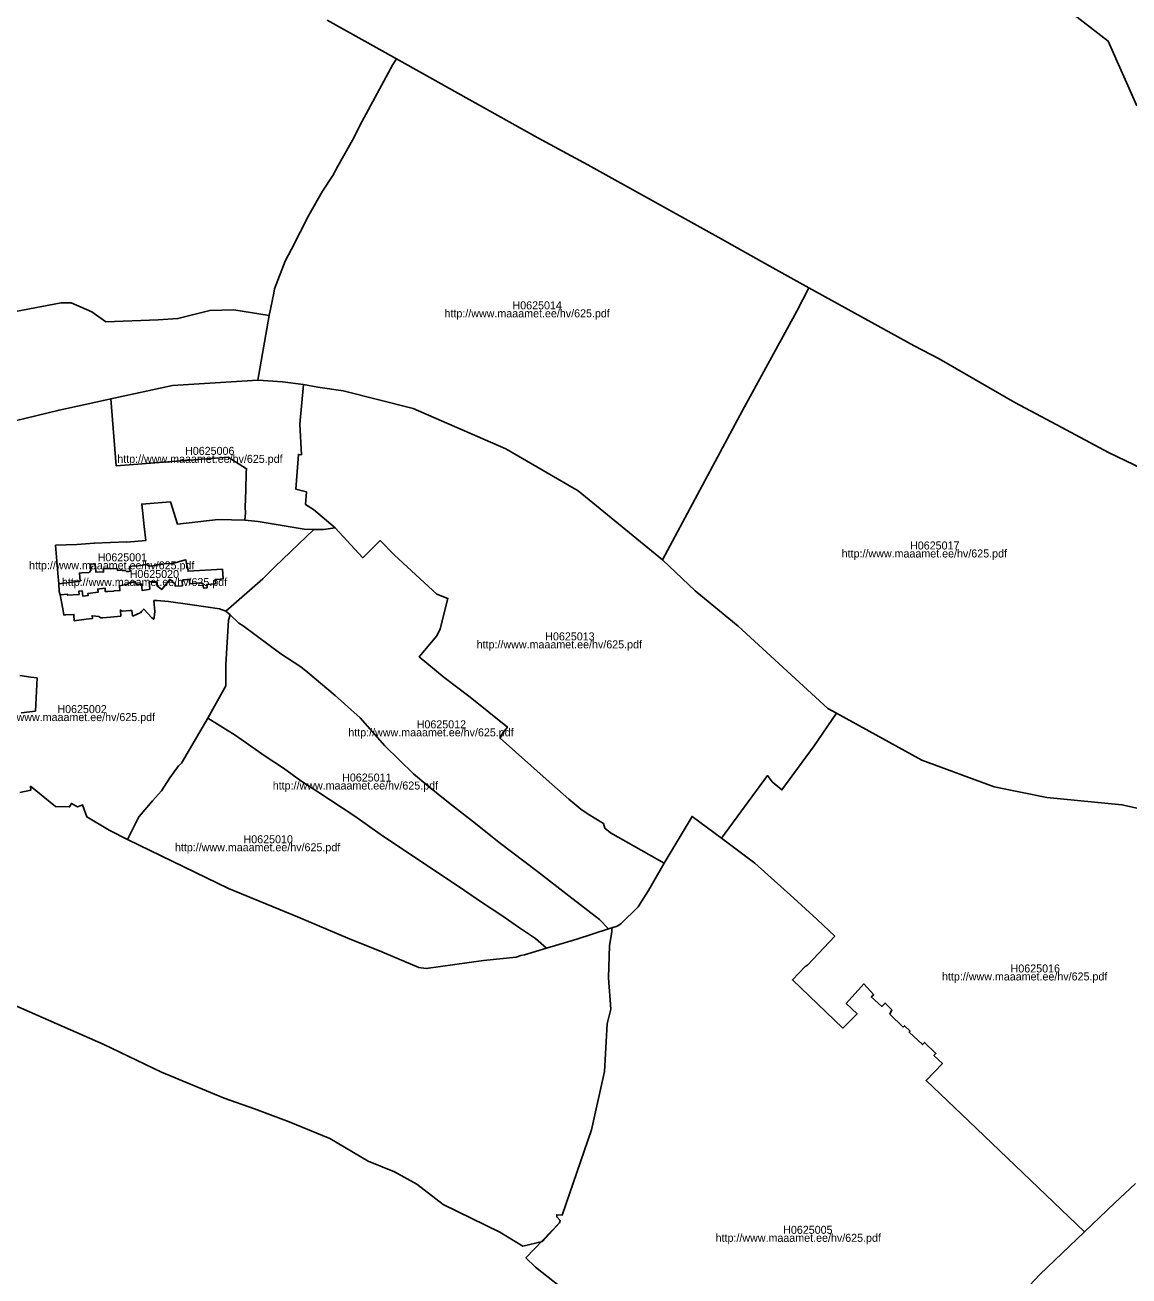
# Model space of a CAD drawing. Extents: x 369010 to 739155, y 6377141 to 6634081.
# Drawn here: x 528995 to 532445, y 6469504 to 6473413 of the extents above; entities that cross this region are included whole.
import ezdxf

# ---------------------------------------------------------------- set-up
doc = ezdxf.new("R2010")
doc.units = 0
for name, color, linetype in [('H_LINK', 7, 'Continuous'), ('H_PIIR', 7, 'Continuous'), ('H_TUNNUS', 7, 'Continuous')]:
    doc.layers.add(name, color=color, linetype=linetype)

msp = doc.modelspace()

# ---------------------------------------------------------------- linework, layer by layer
at = {"layer": 'H_PIIR'}
for points in [[(532469.6799, 6473160.7601), (532380.8399, 6473363), (532136.3301, 6473552.5401)], [(532136.3301, 6473552.5401), (532380.8399, 6473363), (532469.6799, 6473160.7601)], [(529939.2001, 6473428.33), (530156.6701, 6473307.9101), (530144.9, 6473289.3799), (530047.4799, 6473110.31), (530019.01, 6473053.3499), (529972.43, 6472971.79), (529956.8999, 6472943.3101), (529924.5499, 6472894.1199), (529881.85, 6472819.04), (529827.5, 6472712.8899), (529808.0899, 6472675.35), (529774.44, 6472588.62), (529773.15, 6472575.6699), (529758.4499, 6472505.71), (529758.33, 6472505.15), (529648.1, 6472522.84), (529572.37, 6472521.4499), (529472.8699, 6472495.68), (529411.2401, 6472492.2), (529247.44, 6472485.95), (529203.63, 6472516.58), (529139.78, 6472545.1301), (529107.85, 6472545.1301), (528965.28, 6472517.9799)], [(532461.29, 6472038.9899), (532381.79, 6472077.7801), (532219.7999, 6472163.57), (532089.11, 6472233.85), (531852.23, 6472370.04), (531774.5101, 6472410.35), (531444.78, 6472592.07), (531323.01, 6472659.61), (531161.88, 6472750.13), (530754.18, 6472976.5899), (530597.5001, 6473060.8499), (530347.4999, 6473199.9901), (530156.6701, 6473307.9101), (529939.2001, 6473428.33)], [(528965.28, 6472517.9799), (529107.85, 6472545.1301), (529139.78, 6472545.1301), (529203.63, 6472516.58), (529247.44, 6472485.95), (529411.2401, 6472492.2), (529472.8699, 6472495.68), (529572.37, 6472521.4499), (529648.1, 6472522.84), (529758.33, 6472505.15), (529722.2601, 6472303.61), (529456.39, 6472287.1099), (529263, 6472245.1501), (529240.04, 6472240.17), (529101.44, 6472210.1), (528718.62, 6472116.9799)], [(528718.62, 6472116.9799), (529101.44, 6472210.1), (529240.04, 6472240.17), (529263, 6472245.1501), (529280.03, 6472036.1199), (529629.7599, 6472062.6499), (529687.39, 6472026.8899), (529686.68, 6472014.8901), (529684.97, 6471959.33), (529682.9901, 6471906.9199), (529683.76, 6471888.69), (529682.2899, 6471866.42), (529598.33, 6471868.2599), (529472.15, 6471853.4001), (529449.47, 6471923.2401), (529360.08, 6471916.2001), (529367.01, 6471846.09), (529372.6001, 6471802.5199), (529313.1301, 6471797.3199), (529313.77, 6471798.07), (529211.7, 6471794.12), (529211.4599, 6471794.04), (529156.6699, 6471789.53), (529090.9299, 6471787.66), (529097.57, 6471700.68), (529100.4, 6471666.9399), (529102.3599, 6471643.64), (529104.54, 6471632.4001), (529112.9201, 6471589.25), (529116.2799, 6471569.79), (529123.01, 6471569.9199), (529148.1401, 6471571.6399), (529148.88, 6471551.76), (529186.1401, 6471556.6999), (529205.7601, 6471558.61), (529204.81, 6471567.2001), (529216.1401, 6471565.69), (529225.71, 6471565.4001), (529231.7401, 6471560.39), (529237.25, 6471561.3199), (529261.99, 6471563.0099), (529294.1401, 6471566.42), (529293.25, 6471585.0401), (529299.06, 6471581.34), (529323.5001, 6471583.66), (529328.9, 6471584.09), (529331.33, 6471566.74), (529333.99, 6471567.45), (529355.2501, 6471576.8), (529356.05, 6471576.4701), (529360.53, 6471582.1401), (529366.4, 6471588.31), (529391.4799, 6471561.21), (529396.93, 6471556.6), (529398.4701, 6471562.0101), (529400.46, 6471580.8799), (529397.9801, 6471614.64), (529407.97, 6471615.34), (529443.33, 6471612.32), (529517.77, 6471601.6699), (529602.7401, 6471589.1001), (529623.08, 6471582), (529635.92, 6471569.78), (529631.39, 6471554.03), (529622.67, 6471415.25), (529623.0001, 6471347.9501), (529566.69, 6471247.5701), (529484.17, 6471107.2499), (529474.47, 6471098.1601), (529448.0499, 6471060.41), (529421.86, 6471019.81), (529393.7499, 6470988.6), (529352.3901, 6470940.12), (529346.5701, 6470930.7301), (529315.23, 6470868.71), (529257.7601, 6470897.1499), (529187.9301, 6470938.7699), (529175.0699, 6470976.4001), (529171.0999, 6470974.4599), (529159.37, 6470970.65), (529140.0301, 6470981.08), (529134.53, 6470970.2), (529090.69, 6470970.82), (529012.3, 6471034.85), (529013.1301, 6471021.9901), (528979.13, 6471015.5401)], [(528979.0901, 6471380.45), (529013.18, 6471374.9899), (529032.99, 6471373.2499), (529027.5701, 6471269.4401), (528983.26, 6471264.5)], [(528983.26, 6471264.5), (529027.5701, 6471269.4401), (529032.99, 6471373.2499), (529013.18, 6471374.9899), (528979.0901, 6471380.45)], [(532466, 6469793.78), (532399.72, 6469732.2), (532306.28, 6469642.7799), (531944.6599, 6469988.4799), (531811.2899, 6470114.68), (531862.36, 6470168.12), (531835.94, 6470193.2499), (531841.9399, 6470199.96), (531806.1299, 6470234.16), (531799.71, 6470227.4401), (531758.3099, 6470266.6301), (531761.3101, 6470269.76), (531743.8799, 6470286.39), (531739.9501, 6470282.2601), (531698.3201, 6470322.39), (531704.1801, 6470335.52), (531683.14, 6470356.8), (531672.77, 6470346.7199), (531640.0801, 6470376.1899), (531647.73, 6470383.34), (531616.9701, 6470416.98), (531561.71, 6470356.26), (531595.86, 6470323.57), (531551.1499, 6470279.17), (531393.54, 6470429.2799), (531433.24, 6470470.9001), (531441.13, 6470475.9699), (531525.8201, 6470566.48), (531470.4501, 6470618.4), (531398.1, 6470685.26), (531276.5601, 6470793.8999), (531172.24, 6470872.4601), (531316.15, 6471067.69), (531330.6599, 6471048.21), (531360.46, 6471022.91), (531461.1701, 6471160.73), (531531.5199, 6471262.76), (531798.1099, 6471116.05), (532024.04, 6471032.9601), (532189.06, 6470999.72), (532423.29, 6470976.67), (532513.1101, 6470956.7901)], [(528979.13, 6471015.5401), (529013.1301, 6471021.9901), (529012.3, 6471034.85), (529090.69, 6470970.82), (529134.53, 6470970.2), (529140.0301, 6470981.08), (529159.37, 6470970.65), (529171.0999, 6470974.4599), (529175.0699, 6470976.4001), (529187.9301, 6470938.7699), (529257.7601, 6470897.1499), (529315.23, 6470868.71), (529631.5801, 6470714.75), (529846.2601, 6470626.6299), (530003.6299, 6470560.1), (530110.7, 6470517.38), (530178.78, 6470487.6601), (530226.4301, 6470467.84), (530249.33, 6470465.37), (530428.24, 6470490.21), (530530.36, 6470500.47), (530544.8599, 6470505.61), (530556.62, 6470507.47), (530625.46, 6470529), (530719.6299, 6470556.8099), (530818.81, 6470588.93), (530829.07, 6470592.42), (530828.7099, 6470579.61), (530821.8399, 6470537.47), (530818.65, 6470435.82), (530826.4299, 6470338.0399), (530814.55, 6470291.9399), (530805.8301, 6470143.2401), (530765.4101, 6469961.22), (530673.6075, 6469693.9927), (530656.9601, 6469695.62), (530656.9601, 6469688.85), (530668.03, 6469677.77), (530665.341, 6469669.9427), (530612.5151, 6469612.1542), (530551.0472, 6469597.9678), (530479.5301, 6469640.8568), (530301.7298, 6469727.6403), (530219.1796, 6469791.1405), (530150.3878, 6469829.2405), (530067.8377, 6469863.1073), (529948.2457, 6469934.0157), (529820.1872, 6469985.8742), (529712.2369, 6470026.0909), (529618.0451, 6470059.9577), (529421.1947, 6470141.4495), (529239.161, 6470228.233), (528923.777, 6470366.8749)], [(531019.652, 6469193.3816), (530591.0262, 6469532.049), (530560.599, 6469561.1532), (530665.341, 6469669.9427), (530668.03, 6469677.77), (530656.9601, 6469688.85), (530656.9601, 6469695.62), (530673.6101, 6469694), (530765.4101, 6469961.22), (530805.8301, 6470143.2401), (530814.55, 6470291.9399), (530826.4299, 6470338.0399), (530818.65, 6470435.82), (530821.8399, 6470537.47), (530828.7099, 6470579.61), (530829.07, 6470592.42), (530845.38, 6470597.8301), (530856.79, 6470604.96), (530911.66, 6470657.94), (530921.98, 6470674.24), (530944.2501, 6470708.36), (530992.5399, 6470794.76), (531079.7599, 6470940.17), (531172.24, 6470872.4601), (531276.5601, 6470793.8999), (531398.1, 6470685.26), (531470.4501, 6470618.4), (531525.8201, 6470566.48), (531441.13, 6470475.9699), (531433.24, 6470470.9001), (531393.54, 6470429.2799), (531551.1499, 6470279.17), (531595.86, 6470323.57), (531561.71, 6470356.26), (531616.9701, 6470416.98), (531647.73, 6470383.34), (531640.0801, 6470376.1899), (531672.77, 6470346.7199), (531683.14, 6470356.8), (531704.1801, 6470335.52), (531698.3201, 6470322.39), (531739.9501, 6470282.2601), (531743.8799, 6470286.39), (531761.3101, 6470269.76), (531758.3099, 6470266.6301), (531799.71, 6470227.4401), (531806.1299, 6470234.16), (531841.9399, 6470199.96), (531835.94, 6470193.2499), (531862.36, 6470168.12), (531811.2899, 6470114.68), (531944.6599, 6469988.4799), (532306.28, 6469642.7799), (532166.63, 6469509.1201), (532021.8799, 6469354.4401)], [(532643.2723, 6467471.2918), (532234.0919, 6467984.2334), (531906.0079, 6468383.755), (531469.4446, 6468849.4226), (531441.6633, 6468874.5581), (531469.4446, 6468895.7248), (531684.5701, 6469055.26), (531684.69, 6469055.8), (531734.52, 6469100.32), (531737.9, 6469098.8701), (531743.1, 6469107.9799), (531891.93, 6469240.91), (532021.8799, 6469354.4401), (532166.63, 6469509.1201), (532306.28, 6469642.7799), (532399.72, 6469732.2), (532466, 6469793.78)]]:
    msp.add_lwpolyline(points, dxfattribs=at)
for points in [[(530156.6701, 6473307.9101), (530347.4999, 6473199.9901), (530597.5001, 6473060.8499), (530754.18, 6472976.5899), (531161.88, 6472750.13), (531323.01, 6472659.61), (531444.78, 6472592.07), (531407.06, 6472519.33), (531237.02, 6472208.7801), (530987.74, 6471741.71), (530723.7199, 6471958.07), (530497.78, 6472088.8001), (530208.72, 6472215.1001), (529989.11, 6472270.4901), (529910.49, 6472282.15), (529865.57, 6472289.77), (529800.37, 6472298.7501), (529723.63, 6472303.7), (529722.2601, 6472303.61), (529758.33, 6472505.15), (529758.4499, 6472505.71), (529773.15, 6472575.6699), (529774.44, 6472588.62), (529808.0899, 6472675.35), (529827.5, 6472712.8899), (529881.85, 6472819.04), (529924.5499, 6472894.1199), (529956.8999, 6472943.3101), (529972.43, 6472971.79), (530019.01, 6473053.3499), (530047.4799, 6473110.31), (530144.9, 6473289.3799)], [(531444.78, 6472592.07), (531774.5101, 6472410.35), (531852.23, 6472370.04), (532089.11, 6472233.85), (532219.7999, 6472163.57), (532381.79, 6472077.7801), (532461.29, 6472038.9899), (532674.4499, 6471918.4099), (532659.94, 6471831.68), (532573.0201, 6471345.6601), (532513.1101, 6470956.7901), (532423.29, 6470976.67), (532189.06, 6470999.72), (532024.04, 6471032.9601), (531798.1099, 6471116.05), (531531.5199, 6471262.76), (531503.72, 6471277.71), (531223.9799, 6471535.2899), (531089.84, 6471645.6401), (530987.74, 6471741.71), (531237.02, 6472208.7801), (531407.06, 6472519.33)], [(529722.2601, 6472303.61), (529723.63, 6472303.7), (529800.37, 6472298.7501), (529865.57, 6472289.77), (529854.45, 6472166.0801), (529859.73, 6472070.4), (529849.7401, 6472071.3899), (529841.82, 6471962.4001), (529874.4599, 6471954.9201), (529871.33, 6471915.4), (529896.3199, 6471899.78), (529964.75, 6471842.08), (529927.77, 6471836.88), (529897.27, 6471836.44), (529867.31, 6471838.09), (529723.52, 6471862.0701), (529682.2899, 6471866.42), (529683.76, 6471888.69), (529682.9901, 6471906.9199), (529684.97, 6471959.33), (529686.68, 6472014.8901), (529687.39, 6472026.8899), (529629.7599, 6472062.6499), (529280.03, 6472036.1199), (529263, 6472245.1501), (529456.39, 6472287.1099)], [(529865.57, 6472289.77), (529910.49, 6472282.15), (529989.11, 6472270.4901), (530208.72, 6472215.1001), (530497.78, 6472088.8001), (530723.7199, 6471958.07), (530987.74, 6471741.71), (531089.84, 6471645.6401), (531223.9799, 6471535.2899), (531503.72, 6471277.71), (531531.5199, 6471262.76), (531461.1701, 6471160.73), (531360.46, 6471022.91), (531330.6599, 6471048.21), (531316.15, 6471067.69), (531172.24, 6470872.4601), (531079.7599, 6470940.17), (530992.5399, 6470794.76), (530824.8501, 6470888.97), (530807.4601, 6470903.75), (530803.12, 6470918.0099), (530755.31, 6470947.04), (530732.5001, 6470963.34), (530695.0101, 6470993.91), (530624.0601, 6471056.87), (530480.06, 6471185.0699), (530488.76, 6471201.3701), (530502.8801, 6471219.7099), (530386.2701, 6471313.2499), (530305.32, 6471374.3799), (530227.31, 6471439.25), (530282.12, 6471504.47), (530292.2901, 6471526.7299), (530316.88, 6471621.73), (530282.12, 6471635.2401), (530149.55, 6471756.3699), (530105.05, 6471802.4799), (530051.17, 6471748.48), (529964.75, 6471842.08), (529896.3199, 6471899.78), (529871.33, 6471915.4), (529874.4599, 6471954.9201), (529841.82, 6471962.4001), (529849.7401, 6472071.3899), (529859.73, 6472070.4), (529854.45, 6472166.0801)], [(529100.4, 6471666.9399), (529097.57, 6471700.68), (529090.9299, 6471787.66), (529156.6699, 6471789.53), (529211.4599, 6471794.04), (529211.7, 6471794.12), (529313.77, 6471798.07), (529313.1301, 6471797.3199), (529372.6001, 6471802.5199), (529367.01, 6471846.09), (529360.08, 6471916.2001), (529449.47, 6471923.2401), (529472.15, 6471853.4001), (529598.33, 6471868.2599), (529682.2899, 6471866.42), (529723.52, 6471862.0701), (529867.31, 6471838.09), (529897.27, 6471836.44), (529775.8501, 6471719.83), (529738.69, 6471682.6401), (529623.08, 6471582), (529602.7401, 6471589.1001), (529517.77, 6471601.6699), (529443.33, 6471612.32), (529407.97, 6471615.34), (529397.9801, 6471614.64), (529400.46, 6471580.8799), (529398.4701, 6471562.0101), (529396.93, 6471556.6), (529391.4799, 6471561.21), (529366.4, 6471588.31), (529360.53, 6471582.1401), (529356.05, 6471576.4701), (529355.2501, 6471576.8), (529333.99, 6471567.45), (529331.33, 6471566.74), (529328.9, 6471584.09), (529323.5001, 6471583.66), (529299.06, 6471581.34), (529293.25, 6471585.0401), (529294.1401, 6471566.42), (529261.99, 6471563.0099), (529237.25, 6471561.3199), (529231.7401, 6471560.39), (529225.71, 6471565.4001), (529216.1401, 6471565.69), (529204.81, 6471567.2001), (529205.7601, 6471558.61), (529186.1401, 6471556.6999), (529148.88, 6471551.76), (529148.1401, 6471571.6399), (529123.01, 6471569.9199), (529116.2799, 6471569.79), (529112.9201, 6471589.25), (529104.54, 6471632.4001), (529116.8199, 6471634.18), (529127.8399, 6471635.02), (529128.05, 6471631.32), (529163.87, 6471634.19), (529163.0299, 6471644.15), (529174.0401, 6471645.0801), (529175.56, 6471628.8901), (529192.69, 6471630.6801), (529191.9401, 6471637.27), (529223.7301, 6471640.9099), (529222.3999, 6471650.8801), (529228.1899, 6471651.8399), (529245.21, 6471653.7101), (529246.0699, 6471643.06), (529254.05, 6471643.65), (529254.09, 6471643.2499), (529273.1499, 6471644.67), (529273.12, 6471645.0601), (529291.85, 6471646.2001), (529290.16, 6471661.2001), (529315.61, 6471666.12), (529325.98, 6471672.44), (529339.48, 6471673.51), (529341.3099, 6471668.85), (529342.23, 6471665.1599), (529359, 6471666.59), (529360.78, 6471646.53), (529380.83, 6471649.5699), (529385.35, 6471650.44), (529382.8901, 6471673.05), (529387.78, 6471673.52), (529404.97, 6471674.81), (529407.94, 6471660.6301), (529419.61, 6471651.4501), (529422.39, 6471649.1001), (529447.36, 6471680.8701), (529452.7301, 6471676.1199), (529457.06, 6471672.8101), (529463.95, 6471666.8399), (529464.2501, 6471660.1101), (529487.53, 6471661.0699), (529486.7099, 6471675.1301), (529488.21, 6471675.23), (529487.9401, 6471679.34), (529500.44, 6471680.2099), (529508.6701, 6471681.2799), (529510.08, 6471667.4999), (529520.2501, 6471668.5599), (529546.1099, 6471670.62), (529546.2601, 6471668.55), (529551.12, 6471669.05), (529552.5701, 6471653.9), (529564.28, 6471654.9201), (529563.6, 6471665.3201), (529590.4, 6471667.5701), (529589.5401, 6471680.8601), (529605.45, 6471682.0101), (529614.46, 6471682.92), (529611.9801, 6471712.95), (529504.8, 6471706.41), (529497.91, 6471741.8799), (529492.9999, 6471740.59), (529475.2301, 6471736.05), (529453.2599, 6471729.58), (529443.5101, 6471731.0401), (529416.09, 6471728.48), (529409.8899, 6471726.4301), (529404.41, 6471725.98), (529404.7099, 6471723.9), (529394.74, 6471723.5201), (529383.18, 6471722.78), (529374.2099, 6471727.4999), (529349, 6471723.72), (529337.4001, 6471722.65), (529337.2299, 6471723.21), (529321.7801, 6471721.63), (529321.89, 6471721.1099), (529323.32, 6471706.52), (529320.0601, 6471706.1399), (529312.4399, 6471705.44), (529308.86, 6471709.1601), (529298.93, 6471708.29), (529298.7501, 6471710.7399), (529294.43, 6471710.3301), (529294.5299, 6471709.3), (529284.67, 6471708.35), (529284.07, 6471714.55), (529263.79, 6471714.48), (529260.4, 6471714.97), (529256.7, 6471715), (529240.8, 6471714.62), (529240.79, 6471704.25), (529216.55, 6471703.74), (529213.98, 6471730.05), (529209.2099, 6471729.8801), (529199.4401, 6471728.89), (529200.33, 6471709.0199), (529195.24, 6471702.6699), (529173.05, 6471701.4899), (529165.07, 6471700.4901), (529167.1001, 6471675.7101)], [(529964.75, 6471842.08), (530051.17, 6471748.48), (530105.05, 6471802.4799), (530149.55, 6471756.3699), (530282.12, 6471635.2401), (530316.88, 6471621.73), (530292.2901, 6471526.7299), (530282.12, 6471504.47), (530227.31, 6471439.25), (530305.32, 6471374.3799), (530386.2701, 6471313.2499), (530502.8801, 6471219.7099), (530488.76, 6471201.3701), (530480.06, 6471185.0699), (530624.0601, 6471056.87), (530695.0101, 6470993.91), (530732.5001, 6470963.34), (530755.31, 6470947.04), (530803.12, 6470918.0099), (530807.4601, 6470903.75), (530824.8501, 6470888.97), (530992.5399, 6470794.76), (530944.2501, 6470708.36), (530921.98, 6470674.24), (530911.66, 6470657.94), (530856.79, 6470604.96), (530845.38, 6470597.8301), (530829.07, 6470592.42), (530818.81, 6470588.93), (530791.06, 6470618.71), (530694.3599, 6470692.06), (530596.8199, 6470767.8), (530476.7599, 6470858.98), (530403.5399, 6470917.9099), (530318.8001, 6470984.13), (530253.71, 6471036.4201), (530209.7101, 6471073.61), (530120.08, 6471160.71), (530042.54, 6471248.1601), (529964.86, 6471317.9501), (529879.21, 6471389.61), (529857.01, 6471407.3301), (529795.02, 6471448.7399), (529677.0899, 6471535.9901), (529663.03, 6471544.6099), (529635.92, 6471569.78), (529623.08, 6471582), (529738.69, 6471682.6401), (529775.8501, 6471719.83), (529897.27, 6471836.44), (529927.77, 6471836.88)], [(529100.4, 6471666.9399), (529167.1001, 6471675.7101), (529165.07, 6471700.4901), (529173.05, 6471701.4899), (529195.24, 6471702.6699), (529200.33, 6471709.0199), (529199.4401, 6471728.89), (529209.2099, 6471729.8801), (529213.98, 6471730.05), (529216.55, 6471703.74), (529240.79, 6471704.25), (529240.8, 6471714.62), (529256.7, 6471715), (529260.4, 6471714.97), (529263.79, 6471714.48), (529284.07, 6471714.55), (529284.67, 6471708.35), (529294.5299, 6471709.3), (529294.43, 6471710.3301), (529298.7501, 6471710.7399), (529298.93, 6471708.29), (529308.86, 6471709.1601), (529312.4399, 6471705.44), (529320.0601, 6471706.1399), (529323.32, 6471706.52), (529321.89, 6471721.1099), (529321.7801, 6471721.63), (529337.2299, 6471723.21), (529337.4001, 6471722.65), (529349, 6471723.72), (529374.2099, 6471727.4999), (529383.18, 6471722.78), (529394.74, 6471723.5201), (529404.7099, 6471723.9), (529404.41, 6471725.98), (529409.8899, 6471726.4301), (529416.09, 6471728.48), (529443.5101, 6471731.0401), (529453.2599, 6471729.58), (529475.2301, 6471736.05), (529492.9999, 6471740.59), (529497.91, 6471741.8799), (529504.8, 6471706.41), (529611.9801, 6471712.95), (529614.46, 6471682.92), (529605.45, 6471682.0101), (529589.5401, 6471680.8601), (529590.4, 6471667.5701), (529563.6, 6471665.3201), (529564.28, 6471654.9201), (529552.5701, 6471653.9), (529551.12, 6471669.05), (529546.2601, 6471668.55), (529546.1099, 6471670.62), (529520.2501, 6471668.5599), (529510.08, 6471667.4999), (529508.6701, 6471681.2799), (529500.44, 6471680.2099), (529487.9401, 6471679.34), (529488.21, 6471675.23), (529486.7099, 6471675.1301), (529487.53, 6471661.0699), (529464.2501, 6471660.1101), (529463.95, 6471666.8399), (529457.06, 6471672.8101), (529452.7301, 6471676.1199), (529447.36, 6471680.8701), (529422.39, 6471649.1001), (529419.61, 6471651.4501), (529407.94, 6471660.6301), (529404.97, 6471674.81), (529387.78, 6471673.52), (529382.8901, 6471673.05), (529385.35, 6471650.44), (529380.83, 6471649.5699), (529360.78, 6471646.53), (529359, 6471666.59), (529342.23, 6471665.1599), (529341.3099, 6471668.85), (529339.48, 6471673.51), (529325.98, 6471672.44), (529315.61, 6471666.12), (529290.16, 6471661.2001), (529291.85, 6471646.2001), (529273.12, 6471645.0601), (529273.1499, 6471644.67), (529254.09, 6471643.2499), (529254.05, 6471643.65), (529246.0699, 6471643.06), (529245.21, 6471653.7101), (529228.1899, 6471651.8399), (529222.3999, 6471650.8801), (529223.7301, 6471640.9099), (529191.9401, 6471637.27), (529192.69, 6471630.6801), (529175.56, 6471628.8901), (529174.0401, 6471645.0801), (529163.0299, 6471644.15), (529163.87, 6471634.19), (529128.05, 6471631.32), (529127.8399, 6471635.02), (529116.8199, 6471634.18), (529104.54, 6471632.4001), (529102.3599, 6471643.64)], [(529635.92, 6471569.78), (529663.03, 6471544.6099), (529677.0899, 6471535.9901), (529795.02, 6471448.7399), (529857.01, 6471407.3301), (529879.21, 6471389.61), (529964.86, 6471317.9501), (530042.54, 6471248.1601), (530120.08, 6471160.71), (530209.7101, 6471073.61), (530253.71, 6471036.4201), (530318.8001, 6470984.13), (530403.5399, 6470917.9099), (530476.7599, 6470858.98), (530596.8199, 6470767.8), (530694.3599, 6470692.06), (530791.06, 6470618.71), (530818.81, 6470588.93), (530719.6299, 6470556.8099), (530625.46, 6470529), (530590.6101, 6470558.9), (530537.78, 6470594.76), (530484.9601, 6470631.1599), (530421.3299, 6470672.44), (530351.88, 6470720.7001), (530190.21, 6470827.26), (530105.6, 6470884.4699), (530025.96, 6470940.75), (529910.01, 6471017.2199), (529856.79, 6471051.75), (529803.33, 6471090.6301), (529745.6999, 6471128.5299), (529651.6599, 6471193.8201), (529566.69, 6471247.5701), (529623.0001, 6471347.9501), (529622.67, 6471415.25), (529631.39, 6471554.03)], [(529566.69, 6471247.5701), (529651.6599, 6471193.8201), (529745.6999, 6471128.5299), (529803.33, 6471090.6301), (529856.79, 6471051.75), (529910.01, 6471017.2199), (530025.96, 6470940.75), (530105.6, 6470884.4699), (530190.21, 6470827.26), (530351.88, 6470720.7001), (530421.3299, 6470672.44), (530484.9601, 6470631.1599), (530537.78, 6470594.76), (530590.6101, 6470558.9), (530625.46, 6470529), (530556.62, 6470507.47), (530544.8599, 6470505.61), (530530.36, 6470500.47), (530428.24, 6470490.21), (530249.33, 6470465.37), (530226.4301, 6470467.84), (530178.78, 6470487.6601), (530110.7, 6470517.38), (530003.6299, 6470560.1), (529846.2601, 6470626.6299), (529631.5801, 6470714.75), (529315.23, 6470868.71), (529346.5701, 6470930.7301), (529352.3901, 6470940.12), (529393.7499, 6470988.6), (529421.86, 6471019.81), (529448.0499, 6471060.41), (529474.47, 6471098.1601), (529484.17, 6471107.2499)]]:
    msp.add_lwpolyline(points, close=True, dxfattribs=at)

# ---------------------------------------------------------------- texts
at = {"layer": 'H_LINK'}
for rotation, p in [(0, (530306.2081, 6472499.81)), (360, (529283.4797, 6472045.07)), (360, (531547.4778, 6471749.43)), (0, (529110.3076, 6471660.385)), (0, (530406.6956, 6471465.4091)), (0, (528885.0457, 6471238.1925)), (0, (530005.5942, 6471190.505)), (360, (531861.0733, 6470427.7699))]:
    msp.add_text('http://www.maaamet.ee/hv/625.pdf', height=25, rotation=rotation, dxfattribs=at).set_placement(p)
for p in [(529007.858, 6471712.5), (529769.4219, 6471024.39), (529463.7207, 6470831.47), (531153.4651, 6469611.0251)]:
    msp.add_text('http://www.maaamet.ee/hv/625.pdf', height=25, dxfattribs=at).set_placement(p)
at = {"layer": 'H_TUNNUS'}
for s, rotation, p in [('H0625014', 0, (530518.6868, 6472524.81)), ('H0625006', 360, (529495.3343, 6472070.07)), ('H0625017', 360, (531761.2062, 6471774.43)), ('H0625020', 0, (529322.1621, 6471685.385)), ('H0625013', 0, (530621.0495, 6471490.4091)), ('H0625002', 0, (529096.2746, 6471263.1925)), ('H0625012', 0, (530219.3226, 6471215.505)), ('H0625016', 360, (532075.4273, 6470452.7699))]:
    msp.add_text(s, height=25, rotation=rotation, dxfattribs=at).set_placement(p)
for s, p in [('H0625001', (529222.212, 6471737.5)), ('H0625011', (529986.2752, 6471049.39)), ('H0625010', (529678.0747, 6470856.47)), ('H0625005', (531364.6941, 6469636.0251))]:
    msp.add_text(s, height=25, dxfattribs=at).set_placement(p)

doc.saveas('drawing.dxf')
